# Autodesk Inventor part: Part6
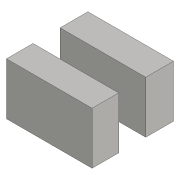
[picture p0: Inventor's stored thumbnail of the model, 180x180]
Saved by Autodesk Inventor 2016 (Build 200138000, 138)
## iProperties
Created: 2015-07
Part Number: Part6
Material: Generic
Document SubType Name: Modeling
Designer: Sandeep
Density: 1 g/cm^3
Appearance: Default
Author: Sandeep
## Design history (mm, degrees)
sketch "Sketch1"
  geometry: L1 (-17.042, 14.133)-(12.609, 14.133); L2 (12.609, 14.133)-(12.609, -14.063); L3 (12.609, -14.063)-(-17.042, -14.063); L4 (-17.042, -14.063)-(-17.042, 14.133); 1 further point
  constraints: 8 end point, 2 parallel, 1 horizontal, 1 perpendicular
extrude "Extrusion1" new body sketch "Sketch1" distance "d0" = 18; taper "d1" = 0 deg
sketch "Sketch2"
  geometry: L1 (-18, 28.196)-(-18, 0) reference; L2 (-18, 9.203)-(0.196, 9.203); L3 (0.196, 9.203)-(0.196, 18.574); L4 (0.196, 18.574)-(-18, 18.574); L5 (-18, 18.574)-(-18, 9.203); 1 further point
  constraints: 8 end point, 2 parallel, 1 horizontal, 1 perpendicular, 1 point on line
extrude "Extrusion2" cut sketch "Sketch2" distance "d2" = 8; taper "d3" = 0 deg
node "Direct Edit1"
body "Solid1"
feature "Delete1"
